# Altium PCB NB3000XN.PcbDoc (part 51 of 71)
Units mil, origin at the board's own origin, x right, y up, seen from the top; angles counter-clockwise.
Board outline 9527.56 x 6929.77 mil, 6 copper layers (Top Layer, GND+SHIELD, MidLayer1, MidLayer2, P2 - 3V3+5V0, Bottom Layer), stack 62.375 mil thick; 832 components, 1027 nets, 4655 pads, 4981 vias.
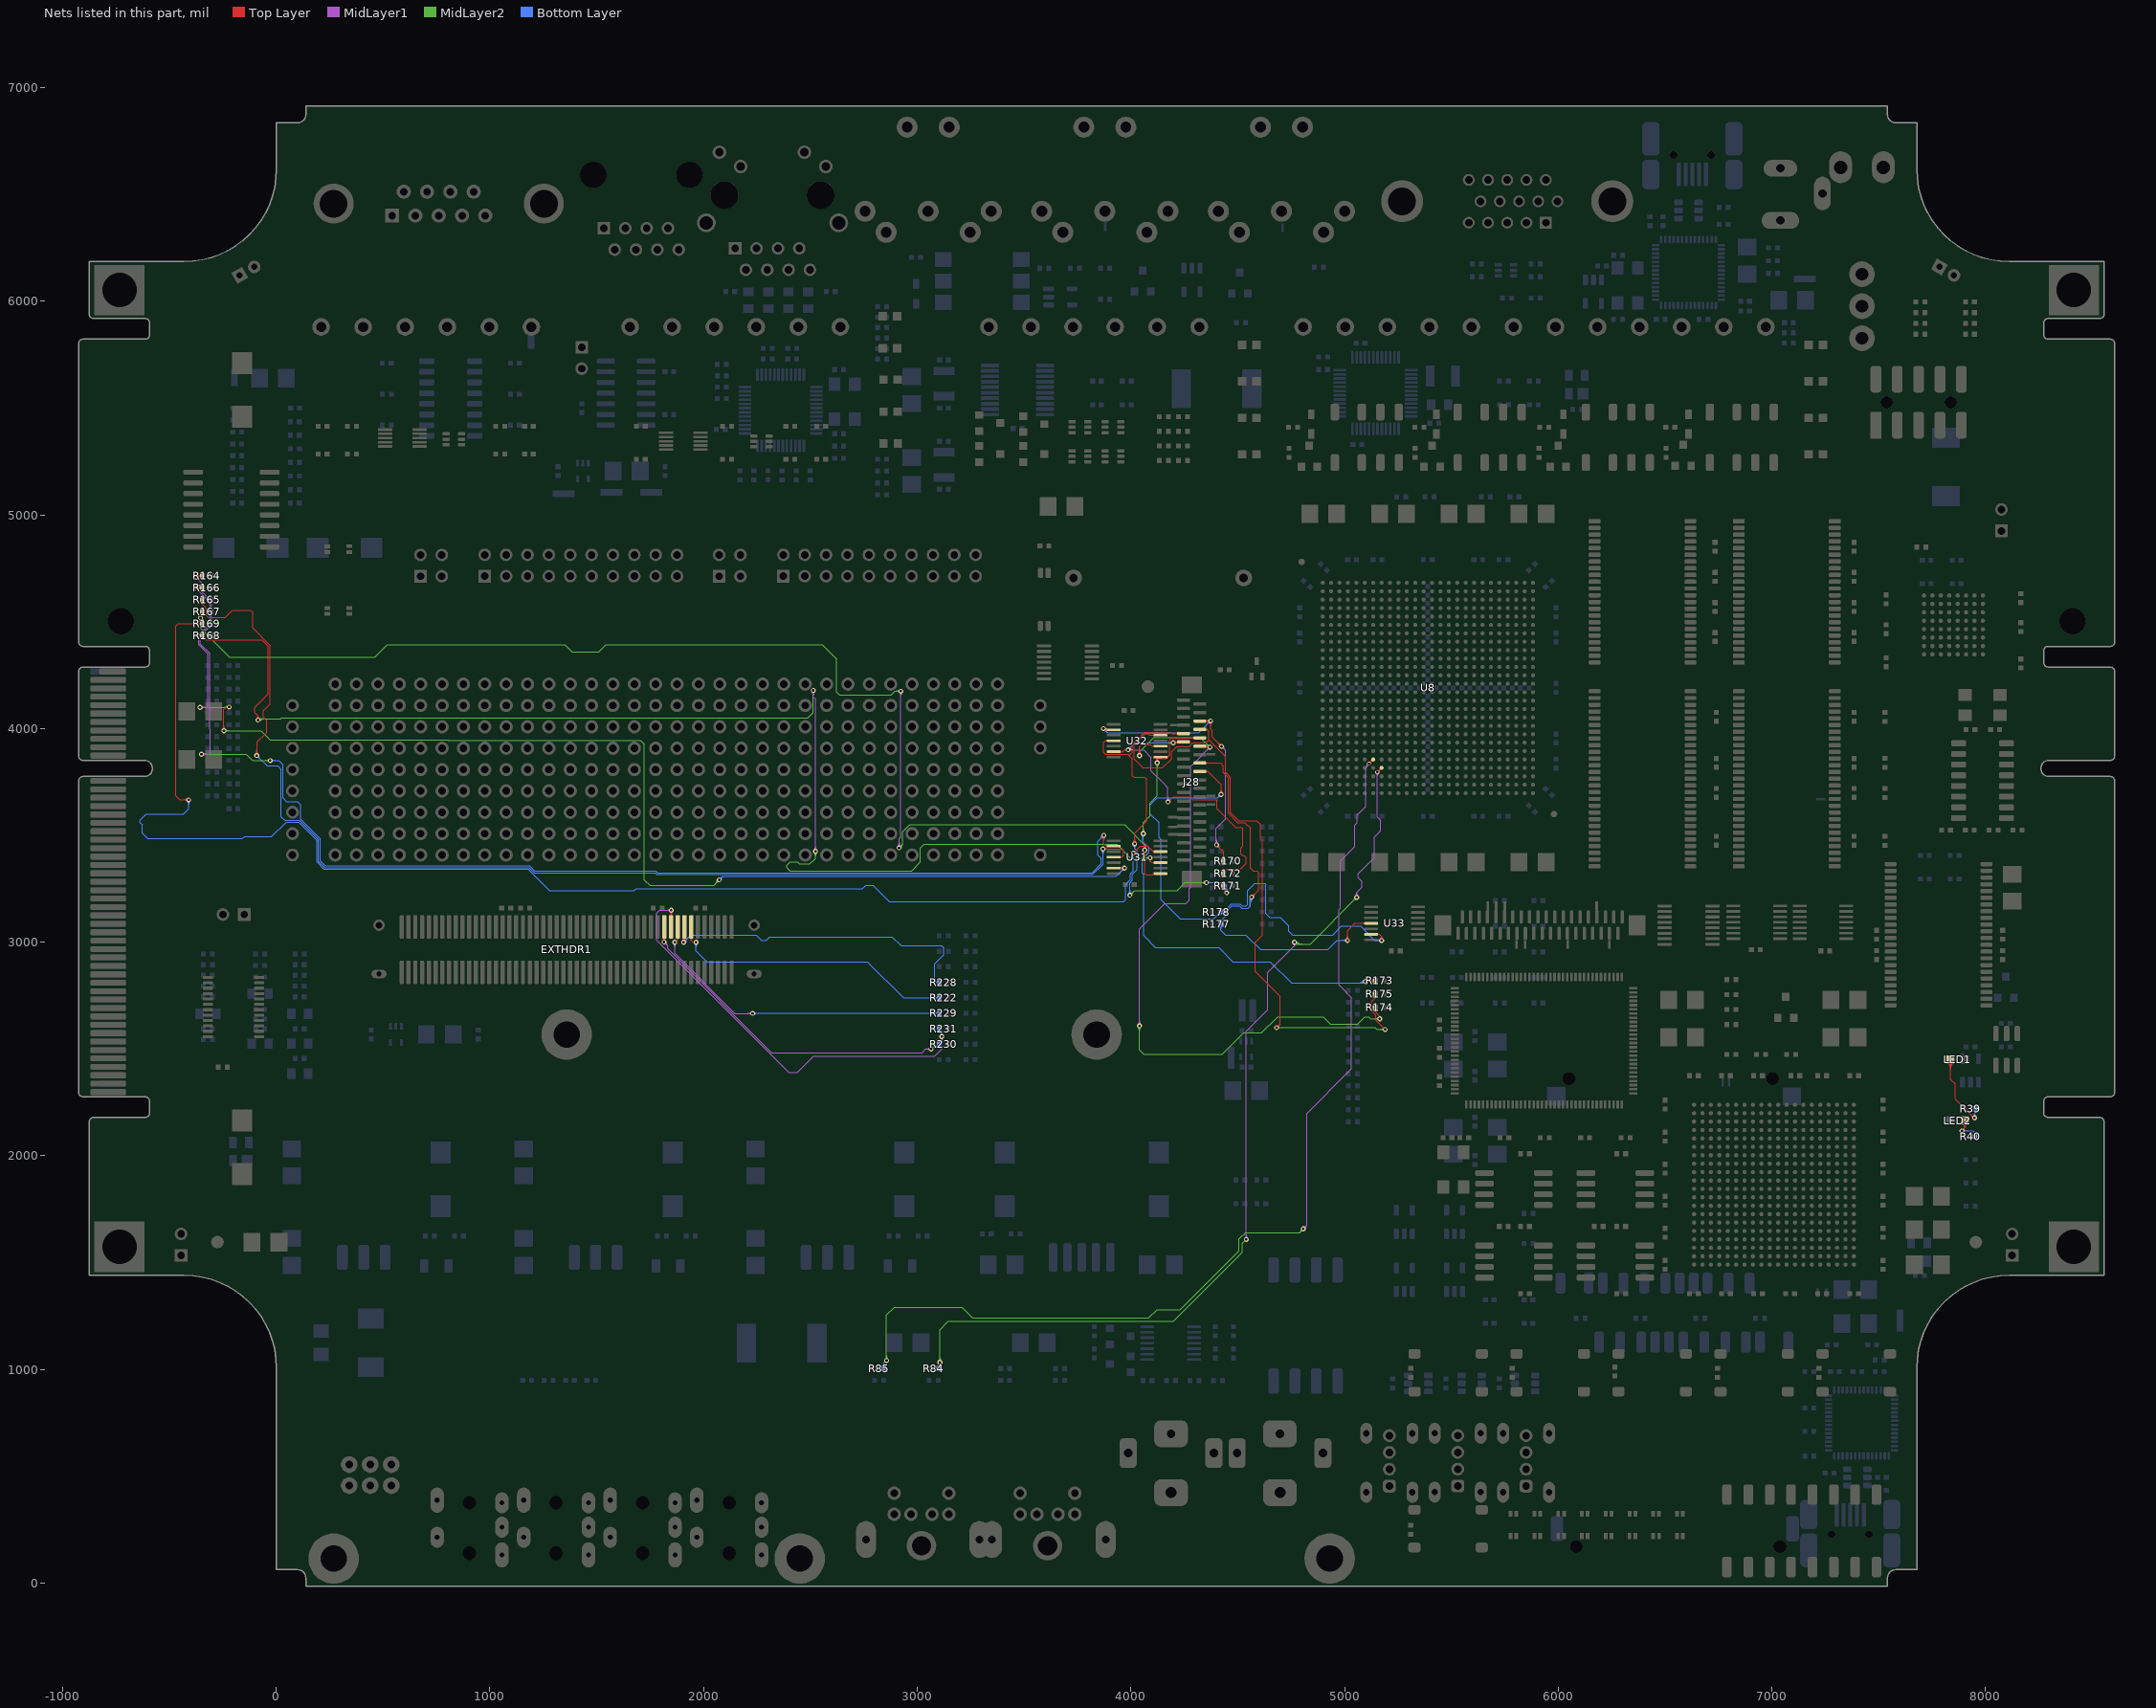
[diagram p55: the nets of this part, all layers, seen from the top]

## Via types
v1: diameter 23, hole 11.81, Top Layer to Bottom Layer, 3672 vias
v2: diameter 26, hole 11.81, Top Layer to Bottom Layer, 461 vias
v3: diameter 19, hole 11.81, Top Layer to Bottom Layer, tented both sides, 396 vias
v4: diameter 23.62, hole 11.81, Top Layer to Bottom Layer, 288 vias
v5: diameter 20, hole 11.81, Top Layer to Bottom Layer, 91 vias
v6: diameter 23, hole 11.81, Top Layer to Bottom Layer, tented both sides, 50 vias
v7: diameter 31, hole 11.81, Top Layer to Bottom Layer, 15 vias
v8: diameter 27.56, hole 11.81, Top Layer to Bottom Layer, tented both sides, 4 vias
v9: diameter 29, hole 11.81, Top Layer to Bottom Layer, 3 vias
v10: diameter 21, hole 11.81, Top Layer to Bottom Layer, 1 vias

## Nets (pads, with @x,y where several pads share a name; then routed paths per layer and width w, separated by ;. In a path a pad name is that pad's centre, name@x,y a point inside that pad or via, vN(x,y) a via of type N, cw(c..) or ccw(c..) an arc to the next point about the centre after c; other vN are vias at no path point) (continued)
JTAG.HARD.TMS: EXTHDR1.13 R222.2 | length 1502
  Top Layer w4: EXTHDR1.13@1936.82,3020.94 cw(c1924.52,3008.04) 1942.35,3008.04 ; EXTHDR1.13@1942.35,3071.85 1942.35,3008.04 ; EXTHDR1.13@1947.87,3020.94 ccw(c1960.18,3008.04) 1942.35,3008.04 ; v1(1965.19,3000.04) 1950.35,3000.04 1942.35,3008.04
  Bottom Layer w4: v1@1958.47,2993.32 cw(c1942.26,2977.11) 1965.19,2977.11 cw(c1988.13,2977.11) v1@1971.91,2993.32 ; v1@1961.3,2996.15 cw(c1951.91,2986.76) 1965.19,2986.76 cw(c1978.47,2986.76) v1@1969.08,2996.15 ; v1(1965.19,3000.04) 1965.19,2958.37 2015.19,2908.37 2767.07,2908.37 2935.44,2740 R222.2@3103.82,2740 ; R222.2@3097.23,2733.41 ccw(c3081.32,2717.5) 3081.32,2740 ccw(c3081.32,2762.5) R222.2@3097.23,2746.59 ; R222.2@3100.06,2736.24 ccw(c3090.98,2727.16) 3090.98,2740 ccw(c3090.98,2752.84) R222.2@3100.06,2743.76
JTAG.SOFT.TCK: EXTHDR1.19 R231.2 | length 2259.8
  Top Layer w4: v1@1841.81,3143.32 cw(c1825.59,3127.11) 1848.52,3127.11 cw(c1871.46,3127.11) v1@1855.24,3143.32 ; EXTHDR1.19@1842.2,3122.62 ccw(c1826.94,3137.89) 1848.52,3137.89 ; v1@1844.64,3146.15 cw(c1835.25,3136.76) 1848.52,3136.76 cw(c1861.8,3136.76) v1@1852.41,3146.15 ; EXTHDR1.19@1845.03,3119.8 ccw(c1836.59,3128.23) 1848.52,3128.23 ; EXTHDR1.19@1847.86,3071.85 1847.86,3091.71 1848.52,3091.71 v1(1848.52,3150.04) ; 1848.52,3134.67 ccw(c1865.56,3134.67) EXTHDR1.19@1853.51,3122.62
  MidLayer1 w4: v1@1840.35,3145.2 ccw(c1831.86,3140.17) 1831.86,3150.04 ccw(c1831.86,3159.91) v1@1840.35,3154.88 ; v1(1848.52,3150.04) 1795.04,3150.04 1781.86,3136.86 1781.86,3008.37 2398.52,2391.71 2440.19,2391.71 2515.19,2466.71 3081.86,2466.71 3115.19,2500.04 v1(3115.19,2558.37) ; v1@3108.47,2551.66 cw(c3092.26,2535.44) 3115.19,2535.44 cw(c3138.13,2535.44) v1@3121.91,2551.66 ; v1@3111.3,2554.49 cw(c3101.91,2545.1) 3115.19,2545.1 cw(c3128.47,2545.1) v1@3119.08,2554.49
  Bottom Layer w4: R231.2@3103.82,2591.71 3103.82,2594.51 R231.2@3103.82,2595 ; R231.2@3103.86,2591.71 3115.19,2580.37 ; R231.2@3104.5,2585.21 cw(c3105.38,2573.33) 3113.81,2581.76 cw(c3119.32,2587.26) R231.2@3112.26,2590.56 ; v1@3108.68,2565.29 ccw(c3094.47,2580.37) 3115.19,2580.37 ; v1@3111.42,2562.38 ccw(c3103.19,2571.11) 3115.19,2571.11 ccw(c3127.19,2571.11) v1@3118.96,2562.38 ; v1(3115.19,2558.37) 3115.19,2580.37 ; v1@3121.7,2565.29 cw(c3135.91,2580.37) 3115.19,2580.37
JTAG.SOFT.TDI: EXTHDR1.15 R228.2 | length 1709.2
  Top Layer w4: v1@1900.14,3006.76 ccw(c1874.28,3032.62) EXTHDR1.15@1910.85,3032.62 ; v1@1902.97,3003.93 ccw(c1883.94,3022.96) EXTHDR1.15@1910.85,3022.96 ; EXTHDR1.15@1905.19,3021.07 cw(c1891.54,3007.42) 1910.85,3007.42 cw(c1930.16,3007.42) EXTHDR1.15@1916.51,3021.07 ; v1@1905.8,3001.1 ccw(c1893.6,3013.3) 1910.85,3013.3 ccw(c1920.15,3013.34) v1@1913.57,3006.76 ; v1(1906.86,3000.04) 1910.85,3004.03 EXTHDR1.15@1910.85,3071.85
  Bottom Layer w4: v1(1906.86,3000.04) 1940.52,3033.71 2246.86,3033.71 2272.19,3008.37 2293.37,3008.37 2310.37,3025.37 2882.39,3025.37 2924.39,2983.37 3113.86,2983.37 3123.52,2973.71 3123.52,2941.71 3081.86,2900.04 3081.86,2820.83 3090.19,2812.5 ; v1@1906.86,3005.54 ccw(c1906.86,3018.82) 1916.25,3009.43 ccw(c1925.64,3000.04) v1@1912.36,3000.04 ; v1@1906.86,3009.54 ccw(c1906.86,3032.48) 1923.07,3016.26 ccw(c1939.29,3000.04) v1@1916.36,3000.04 ; R228.2@3095.13,2809.12 ccw(c3090.19,2807.19) 3090.19,2812.5 ; R228.2@3095.13,2815.88 cw(c3090.19,2817.81) 3090.19,2812.5 ; R228.2@3103.82,2812.5 3090.19,2812.5
JTAG.SOFT.TDO: EXTHDR1.17 R229.2 | length 1716.4
  Top Layer w4: v1(1865.19,3000.04) 1879.35,3014.2 ; EXTHDR1.17@1875.99,3019.47 cw(c1873.55,3014.21) 1879.35,3014.21 ; EXTHDR1.17@1879.35,3071.85 1879.35,3014.2 ; EXTHDR1.17@1882.72,3019.47 ccw(c1885.16,3014.21) 1879.35,3014.21
  MidLayer1 w4: v1@1858.47,2993.32 cw(c1842.26,2977.11) 1865.19,2977.11 cw(c1888.13,2977.11) v1@1871.91,2993.32 ; v1@1861.3,2996.15 cw(c1851.91,2986.76) 1865.19,2986.76 cw(c1878.47,2986.76) v1@1869.08,2996.15 ; v1(1865.19,3000.04) 1865.19,2975 1865.19,2947.67 2146.15,2666.71 v1(2229.86,2666.71) ; v1@2223.14,2659.99 ccw(c2206.92,2643.77) 2206.92,2666.71 ccw(c2206.92,2689.64) v1@2223.14,2673.43 ; v1@2225.97,2662.82 ccw(c2216.58,2653.43) 2216.58,2666.71 ccw(c2216.58,2679.99) v1@2225.97,2670.6
  Bottom Layer w4: v1(2229.86,2666.71) 2230.65,2667.5 R229.2@3103.82,2667.5 ; v1@2233.75,2662.82 cw(c2245.05,2651.52) 2245.05,2667.5 ; v1@2236.57,2659.99 cw(c2254.7,2641.86) 2254.7,2667.5 ; v1@2236.57,2673.43 ccw(c2250.88,2687.73) 2250.88,2667.5 ; R229.2@3097.23,2660.91 ccw(c3081.32,2645) 3081.32,2667.5 ccw(c3081.32,2690) R229.2@3097.23,2674.09 ; R229.2@3100.06,2663.74 ccw(c3090.98,2654.66) 3090.98,2667.5 ccw(c3090.98,2680.34) R229.2@3100.06,2671.26
JTAG.SOFT.TMS: EXTHDR1.21 R230.2 | length 1926.8
  Top Layer w4: v1@1808.47,3007.43 ccw(c1789.43,3026.47) EXTHDR1.21@1816.36,3026.47 ; EXTHDR1.21@1810.7,3021.07 cw(c1797.05,3007.42) 1816.36,3007.42 cw(c1835.67,3007.42) EXTHDR1.21@1822.02,3021.07 ; v1@1811.3,3004.6 ccw(c1799.08,3016.82) EXTHDR1.21@1816.36,3016.82 ; v1(1815.19,3000.71) 1816.36,3001.88 EXTHDR1.21@1816.36,3071.85 ; EXTHDR1.21@1816.36,3020.81 ccw(c1835.3,3020.81) v1@1821.91,3007.43
  MidLayer1 w4: v1(1815.19,3000.71) 1831.33,2984.57 ; v1@1815.22,2991.21 cw(c1815.31,2968.56) 1831.32,2984.57 ; v1@1815.21,2995.21 cw(c1815.26,2982.09) 1824.53,2991.37 cw(c1833.8,3000.64) v1@1820.69,3000.69 ; v1@1824.69,3000.67 ccw(c1847.34,3000.59) 1831.32,2984.57 ; v1@3058.47,2493.32 ccw(c3042.26,2477.11) 3042.26,2500.04 ccw(c3042.26,2522.98) v1@3058.47,2506.76 ; v1@3061.3,2496.15 ccw(c3051.91,2486.76) 3051.91,2500.04 ccw(c3051.91,2513.32) v1@3061.3,2503.93 ; v1(3065.19,2500.04) 3040,2500.04 3023,2483.04 2318.51,2483.04 1831.33,2970.22 1831.33,2984.57
  Bottom Layer w4: v1(3065.19,2500.04) 3075.19,2510.04 ; 3080.57,2510.04 ccw(c3080.57,2529) R230.2@3098.73,2523.54 ; 3085.95,2510.04 ccw(c3085.95,2527.38) R230.2@3102.56,2522.39 ; 3091.33,2510.04 ccw(c3091.33,2525.76) R230.2@3106.39,2521.24 ; R230.2@3094.89,2524.69 cw(c3075.19,2530.62) 3075.19,2510.04 ; 3096.71,2510.04 ccw(c3096.71,2524.15) R230.2@3110.22,2520.08 ; 3102.09,2510.04 ccw(c3102.09,2522.53) R230.2@3114.05,2518.93 ; R230.2@3103.82,2522.5 3103.82,2510.04 3075.19,2510.04
KEYBOARD.CLOCK: R85.1 U8.AB7 | length 5179.3
  Top Layer w4: v3(5114.41,3835.67) U8.AB7@5134.09,3855.35 ; U8.AB7@5126.59,3855.35 cw(c5108.49,3855.35) 5121.29,3842.55 cw(c5134.09,3829.75) U8.AB7@5134.09,3847.85 ; U8.AB7@5126.75,3855.35 cw(c5109.03,3855.35) 5121.56,3842.82 cw(c5134.09,3830.29) U8.AB7@5134.09,3848.01 ; 5127.21,3848.47 cw(c5114.41,3861.28) 5114.41,3843.17 ccw(c5114.41,3861.28) 5127.21,3848.47 ; 5127.21,3848.47 ccw(c5140.02,3835.67) 5121.91,3835.67 cw(c5140.02,3835.67) 5127.21,3848.47
  MidLayer1 w4: v1(4806.86,1658.37) 4823.52,1675.04 4823.52,2198.71 5021.14,2396.33 ; v1@4806.86,1663.87 ccw(c4806.86,1677.15) 4816.25,1667.76 ccw(c4825.64,1658.37) v1@4812.36,1658.37 ; v1@4806.86,1667.87 ccw(c4806.86,1690.81) 4823.08,1674.59 ccw(c4839.29,1658.37) v1@4816.36,1658.37 ; 5020,2395 5033.52,2408.52 5033.52,2740.04 4973.52,2800.04 4973.52,3152.33 4981.19,3160 4981.19,3380.06 5048.52,3447.39 5048.52,3548.69 5060,3560.16 5060,3597.2 5070,3607.2 ; 5070.03,3607.17 5098.9,3636.04 5098.9,3660 5098.9,3670 5098.9,3718.62 5098.9,3812.16 cw(c5112.95,3812.16) 5103.02,3822.09 ; v3@5106.94,3835.02 cw(c5088.9,3833.44) 5102.77,3821.8 cw(c5116.64,3810.16) v3@5115.06,3828.2
  MidLayer2 w4: v1@2850.14,1048.43 ccw(c2833.92,1064.64) 2856.86,1064.64 ccw(c2879.79,1064.64) v1@2863.57,1048.43 ; v1@2852.97,1045.6 ccw(c2843.58,1054.99) 2856.86,1054.99 ccw(c2870.14,1054.99) v1@2860.75,1045.6 ; v1(2856.86,1041.71) 2856.86,1255 2892.73,1290.87 3210,1290.87 3259.83,1241.04 4083.65,1241.04 4122.33,1279.73 4230.79,1279.73 4506.64,1555.58 4506.64,1610.88 4537.13,1641.37 4789.86,1641.37 v1(4806.86,1658.37) ; v1@4797.36,1658.37 cw(c4774.42,1658.37) 4790.64,1642.16 cw(c4806.86,1625.94) v1@4806.86,1648.87 ; v1@4801.36,1658.37 cw(c4788.08,1658.37) 4797.47,1648.99 cw(c4806.86,1639.6) v1@4806.86,1652.87
  Bottom Layer w4: R85.1@2836.64,1012.08 ccw(c2820.73,1027.99) 2843.23,1027.99 ccw(c2865.73,1027.99) R85.1@2849.82,1012.08 ; R85.1@2839.47,1009.25 ccw(c2830.39,1018.33) 2843.23,1018.33 ccw(c2856.07,1018.33) R85.1@2846.99,1009.25 ; R85.1@2843.23,1005 2843.23,1028.08 v1(2856.86,1041.71)
KEYBOARD.DATA: R84.1 U8.AC8 | length 5037
  Top Layer w4: v3(5153.78,3796.3) U8.AC8@5173.46,3815.98 ; U8.AC8@5165.96,3815.98 cw(c5147.86,3815.98) 5160.66,3803.18 cw(c5173.46,3790.38) U8.AC8@5173.46,3808.48 ; U8.AC8@5166.12,3815.98 cw(c5148.4,3815.98) 5160.93,3803.45 cw(c5173.46,3790.92) U8.AC8@5173.46,3808.64 ; 5166.58,3809.1 ccw(c5179.39,3796.3) 5161.28,3796.3 cw(c5179.39,3796.3) 5166.58,3809.1 ; 5166.58,3809.1 cw(c5153.78,3821.91) 5153.78,3803.8 ccw(c5153.78,3821.91) 5166.58,3809.1
  MidLayer1 w4: v1@4533.47,1615.09 ccw(c4517.26,1631.31) 4540.19,1631.31 ccw(c4563.13,1631.31) v1@4546.91,1615.09 ; v1@4536.3,1612.26 ccw(c4526.91,1621.65) 4540.19,1621.65 ccw(c4553.47,1621.65) v1@4544.08,1612.26 ; v1(4540.19,1608.37) 4540.19,2583.37 4640.19,2683.37 4640.19,2858.37 4765.19,2983.37 ; v1@4760.35,2991.87 cw(c4755.32,2983.38) 4765.19,2983.38 ; v1(4765.19,3000.04) 4765.19,2983.37 ; v1@4770.03,2991.87 ccw(c4775.06,2983.38) 4765.19,2983.38 ; v1@5050.31,3216.59 ccw(c5035.79,3231.86) 5056.86,3231.86 ; v1@5053.07,3213.69 ccw(c5044.66,3222.53) 5056.86,3222.53 ccw(c5069.05,3222.53) v1@5060.65,3213.69 ; v1(5056.86,3209.71) 5056.86,3231.86 ; v1@5063.4,3216.59 cw(c5077.92,3231.86) 5056.86,3231.86 ; v3@5148.48,3791 cw(c5135.67,3778.19) 5153.78,3778.19 cw(c5171.89,3778.19) v3@5159.08,3791 ; v3@5148.59,3791.11 cw(c5136.05,3778.57) 5153.78,3778.57 cw(c5171.51,3778.57) v3@5158.97,3791.11 ; v3(5153.78,3796.3) 5153.78,3718.62 5153.78,3670 5153.78,3660 5153.78,3586.45 5168.52,3571.71 5168.52,3520.65 5140.86,3492.98 5140.86,3395.36 5080.5,3335 5079.19,3335 5064.19,3320 5064.19,3301.04 5081.86,3283.37 5081.86,3256.86 5056.86,3231.86
  MidLayer2 w4: v1@3100.14,1040.09 ccw(c3083.92,1056.31) 3106.86,1056.31 ccw(c3129.79,1056.31) v1@3113.57,1040.09 ; v1@3102.97,1037.26 ccw(c3093.58,1046.65) 3106.86,1046.65 ccw(c3120.14,1046.65) v1@3110.75,1037.26 ; v1(3106.86,1033.37) 3106.86,1186.86 3145.04,1225.04 4198.73,1225.04 4522.64,1548.95 4522.64,1590.82 v1(4540.19,1608.37) ; v1@4763.42,2998.27 ccw(c4779.27,3014.12) 4779.27,2991.71 ; v1(4765.19,3000.04) 4765.19,2993.37 4766.86,2991.71 4838.86,2991.71 v1(5056.86,3209.71) ; v1@4766.25,3001.1 ccw(c4788.93,3023.78) 4788.93,2991.71 ; v1@4769.08,3003.93 ccw(c4798.59,3033.44) 4798.59,2991.71 ; v1@4771.91,3006.76 ccw(c4808.24,3043.09) 4808.24,2991.71 ; v1@5047.36,3209.71 cw(c5024.42,3209.71) 5040.64,3193.49 cw(c5056.86,3177.27) v1@5056.86,3200.21 ; v1@5051.36,3209.71 cw(c5038.08,3209.71) 5047.47,3200.32 cw(c5056.86,3190.93) v1@5056.86,3204.21
  Bottom Layer w4: R84.1@3094.88,1013.79 ccw(c3084.85,1033.37) v1(3106.86,1033.37) 3106.86,1000.04 3099.13,1000.04 R84.1@3099.13,1005 ; R84.1@3096.71,1010.23 ccw(c3088.2,1026.83) v1@3106.86,1026.83 ; R84.1@3098.53,1006.67 ccw(c3091.55,1020.29) 3106.86,1020.29 ; v1@3100.14,1026.66 cw(c3083.92,1010.44) 3106.86,1010.44 cw(c3129.79,1010.44) v1@3113.57,1026.66 ; v1@3102.97,1029.49 cw(c3093.58,1020.1) 3106.86,1020.1 cw(c3120.14,1020.1) v1@3110.75,1029.49
LED1_BLUE_EXTA: R165.2 U31.4 | length 5977.9
  Top Layer w4: R165.2@-351.93,4595.17 cw(c-361.16,4583.38) -346.18,4583.38 ; R165.2@-346.18,4603 -346.18,4583.37 ; R165.2@-340.44,4595.17 ccw(c-331.2,4583.38) -346.18,4583.38 ; v1@-97.86,3880.43 ccw(c-114.08,3896.64) -91.14,3896.64 ccw(c-68.21,3896.64) v1@-84.43,3880.43 ; v1@-95.03,3877.6 ccw(c-104.42,3886.99) -91.14,3886.99 ccw(c-77.86,3886.99) v1@-87.25,3877.6 ; v1(-91.14,3873.71) -91.14,3902.54 -89,3904.69 -89,3937.16 -45,3981.16 -45,4036.25 -59.81,4051.06 -59.81,4084.13 ; -59.81,4084.81 -59.81,4084.13 ; v1(3869.19,3436.37) 3956.52,3436.37 3967.19,3425.71 3967.19,3408.23 3957.19,3398.23 U31.4@3920,3398.23 ; v1@3873.08,3432.49 cw(c3882.47,3423.1) 3882.47,3436.37 cw(c3882.47,3449.65) v1@3873.08,3440.26 ; v1@3875.91,3429.66 cw(c3892.13,3413.44) 3892.13,3436.37 cw(c3892.13,3459.31) v1@3875.91,3443.09 ; U31.4@3949.31,3395.4 cw(c3956.14,3388.57) 3956.14,3398.23 cw(c3956.14,3407.89) U31.4@3949.31,3401.06 ; -346.18,4583.37 -326.48,4563.67 -326.48,4530 -316.48,4520 -240,4520 -205,4555 -120,4555 -110,4545 -110,4470 -29,4389 -29,4114.94 -59.81,4084.13
  Bottom Layer w4: v1@-91.14,3864.21 cw(c-91.14,3841.27) -74.93,3857.49 cw(c-58.71,3873.71) v1@-81.64,3873.71 ; v1@-91.14,3868.21 cw(c-91.14,3854.93) -81.75,3864.32 cw(c-72.36,3873.71) v1@-85.64,3873.71 ; v1(-91.14,3873.71) -42.48,3825.04 6.86,3825.04 23.52,3808.37 23.52,3586.48 40,3570 108.88,3570 198.52,3480.35 198.52,3400 198.52,3377.98 226.46,3350.04 1181.86,3350.04 1206.86,3325.04 1773.52,3325.04 1781.86,3316.71 3821.71,3316.71 3869.19,3364.19 v1(3869.19,3436.37) ; v1@3862.47,3429.66 cw(c3846.26,3413.44) 3869.19,3413.44 cw(c3892.13,3413.44) v1@3875.91,3429.66 ; v1@3865.3,3432.49 cw(c3855.91,3423.1) 3869.19,3423.1 cw(c3882.47,3423.1) v1@3873.08,3432.49
LED1_GREEN_EXTA: R166.2 U31.6 | length 6570.3
  Top Layer w4: v1(-365,4665) -365,4661.52 v1@-367.52,4659 ; v1@-359.6,4666.05 ccw(c-351.04,4667.73) R166.2@-351.04,4659 ; R166.2@-355.68,4666.82 ccw(c-346.18,4668.67) R166.2@-346.18,4659 v1@-367.52,4659 ; R166.2@-353.02,4652.67 ccw(c-367.52,4639.24) v1@-367.52,4659 ; R166.2@-353.02,4665.33 cw(c-367.52,4678.76) v1@-367.52,4659 ; R166.2@-350.08,4655.39 ccw(c-358.36,4647.72) -358.36,4659 ccw(c-358.36,4670.28) R166.2@-350.08,4662.61 ; v1@-251.72,3996.43 ccw(c-267.94,4012.64) -245,4012.64 ccw(c-222.07,4012.64) v1@-238.28,3996.43 ; v1@-248.89,3993.6 ccw(c-258.28,4002.99) -245,4002.99 ccw(c-231.72,4002.99) v1@-241.11,3993.6 ; v1(-245,3989.71) -245,4090 -235,4100 v1@-225,4100 ; U31.6@3920,3347.05 v1(3970.19,3347.04) ; U31.6@3947.24,3347.05 cw(c3947.24,3324.09) v1@3963.47,3340.32 ; U31.6@3947.27,3347.05 ccw(c3947.27,3369.96) v1@3963.47,3353.76 ; U31.6@3949.31,3344.22 cw(c3956.14,3337.39) 3956.14,3347.05 cw(c3956.14,3356.71) U31.6@3949.31,3349.88 ; 3956.9,3347.05 cw(c3956.9,3333.75) v1@3966.3,3343.15 ; 3956.93,3347.05 ccw(c3956.93,3360.3) v1@3966.3,3350.93 ; v1@-367.52,4659 -376.48,4650.04 v1@-367.52,4659
  MidLayer1 w4: v1@-370.76,4657.44 cw(c-379.62,4645.82) -365,4645.82 ; v1(-365,4665) -365,4645.81 ; v1@-359.24,4657.44 ccw(c-350.38,4645.82) -365,4645.82 ; v1(-356.73,4099.58) -324.42,4099.58 -319,4105 -319,4349 -362.5,4392.5 -362.5,4437.75 -309.62,4490.63 -309.62,4589.37 -310.16,4589.91 ; v1@-352.84,4095.69 cw(c-343.45,4086.31) -343.45,4099.58 cw(c-343.45,4112.86) v1@-352.84,4103.47 ; v1@-350.01,4092.87 cw(c-333.79,4076.65) -333.79,4099.58 cw(c-333.79,4122.52) v1@-350.01,4106.3 ; -309.62,4590.44 -365,4645.81
  MidLayer2 w4: v1(-356.73,4099.58) -356.31,4100 v1@-220,4100 ; v1@-352.84,4095.69 cw(c-342.44,4085.3) -342.44,4100 ; v1@-352.84,4103.47 ccw(c-344.45,4111.86) -344.45,4100 ; v1@-350.01,4092.87 cw(c-332.79,4075.64) -332.79,4100 ; v1@-350.01,4106.3 ccw(c-334.8,4121.51) -334.8,4100 ; -245.35,4100 ccw(c-245.35,4126.35) v1@-226.72,4107.72 ; v1(-245,3989.71) -71.02,3989.71 -29.19,3947.87 802.36,3947.87 805,3945.23 1704.77,3945.23 1723.52,3926.48 1723.52,3291.71 1748.52,3266.71 2048.52,3266.71 v1(2073.52,3291.71) ; v1@-241.11,3985.82 cw(c-231.72,3976.43) -231.72,3989.71 cw(c-231.72,4002.99) v1@-241.11,3993.6 ; -240.52,4100 cw(c-240.52,4080.48) v1@-226.72,4094.28 ; v1@-238.28,3982.99 cw(c-222.07,3966.77) -222.07,3989.71 cw(c-222.07,4012.64) v1@-238.28,3996.43 ; -235.69,4100 ccw(c-235.69,4116.69) v1@-223.89,4104.89 ; v1@2064.02,3291.71 cw(c2041.09,3291.71) 2057.31,3275.49 cw(c2073.52,3259.27) v1@2073.52,3282.21 ; v1@2068.02,3291.71 cw(c2054.75,3291.71) 2064.14,3282.32 cw(c2073.52,3272.93) v1@2073.52,3286.21
  Bottom Layer w4: v1(2073.52,3291.71) 2090.19,3308.37 3931.52,3308.37 v1(3970.19,3347.04) ; v1@2073.52,3297.21 ccw(c2073.52,3310.49) 2082.91,3301.1 ccw(c2092.3,3291.71) v1@2079.02,3291.71 ; v1@2073.52,3301.21 ccw(c2073.52,3324.14) 2089.74,3307.93 ccw(c2105.96,3291.71) v1@2083.02,3291.71 ; v1@3960.69,3347.04 cw(c3937.76,3347.04) 3953.97,3330.82 cw(c3970.19,3314.61) v1@3970.19,3337.54 ; v1@3964.69,3347.04 cw(c3951.41,3347.04) 3960.8,3337.65 cw(c3970.19,3328.26) v1@3970.19,3341.54
  other v1: -220,4101
LED1_RED_EXTA: R164.2 U31.2 | length 6388.5
  Top Layer w4: v1(-376.48,4708.37) -369.85,4715 R164.2@-346.18,4715 ccw(c-346.18,4687.98) v1@-368.6,4703.07 ; v1@-375.23,4707.54 cw(c-361.21,4698.1) -361.21,4715 ; v1@-371.91,4705.3 cw(c-353.7,4693.04) R164.2@-353.7,4715 ; R164.2@-352.77,4708.41 ccw(c-368.68,4692.5) -368.68,4715 ccw(c-368.68,4737.5) R164.2@-352.77,4721.59 ; R164.2@-349.94,4711.24 ccw(c-359.02,4702.16) -359.02,4715 ccw(c-359.02,4727.84) R164.2@-349.94,4718.76 ; v1@3866.81,3493.32 cw(c3850.59,3477.11) 3873.52,3477.11 cw(c3896.46,3477.11) v1@3880.24,3493.32 ; v1@3869.64,3496.15 cw(c3860.25,3486.76) 3873.52,3486.76 cw(c3886.8,3486.76) v1@3877.41,3496.15 ; v1(3873.52,3500.04) 3873.52,3461.4 3885.52,3449.41 ; U31.2@3890.32,3447.01 ccw(c3885.52,3443.41) 3885.52,3449.41 ; U31.2@3890.32,3451.81 cw(c3885.52,3455.41) 3885.52,3449.41 ; U31.2@3920,3449.41 3885.52,3449.41
  MidLayer1 w4: v1@-376.48,4698.87 cw(c-376.48,4675.94) -360.26,4692.16 cw(c-344.04,4708.37) v1@-366.98,4708.37 ; v1@-376.48,4702.87 cw(c-376.48,4689.6) -367.09,4698.99 cw(c-357.7,4708.37) v1@-370.98,4708.37 ; v1(-376.48,4708.37) -345,4676.9 -345,4637.13 -301.62,4593.75 -301.62,4487.31 -354.5,4434.44 -354.5,4395.81 -311,4352.31 -311,3998.61 -309.23,3996.83 -309.23,3887 -316.23,3880 v1(-350,3880) ; v1@-346.11,3876.11 cw(c-336.72,3866.72) -336.72,3880 cw(c-336.72,3893.28) v1@-346.11,3883.89 ; v1@-343.28,3873.28 cw(c-327.07,3857.06) -327.07,3880 cw(c-327.07,3902.93) v1@-343.28,3886.72
  MidLayer2 w4: v1(-350,3880) -140,3880 -118.24,3858.24 -110.04,3850.04 v1(-28.14,3850.04) ; v1@-346.11,3876.11 cw(c-336.72,3866.72) -336.72,3880 cw(c-336.72,3893.28) v1@-346.11,3883.89 ; v1@-343.28,3873.28 cw(c-327.07,3857.06) -327.07,3880 cw(c-327.07,3902.93) v1@-343.28,3886.72 ; v1@-34.86,3843.32 ccw(c-51.08,3827.11) -51.08,3850.04 ccw(c-51.08,3872.98) v1@-34.86,3856.76 ; v1@-32.03,3846.15 ccw(c-41.42,3836.76) -41.42,3850.04 ccw(c-41.42,3863.32) v1@-32.03,3853.93
  Bottom Layer w4: v1(-28.14,3850.04) 11.52,3850.04 31.86,3829.71 31.86,3675.04 48.52,3658.37 98.52,3658.37 115.19,3641.71 115.19,3575 206.86,3483.33 206.86,3380.96 229.78,3358.04 1185.17,3358.04 1210.17,3333.04 1776.84,3333.04 1784.84,3325.04 3818.73,3325.04 3861.19,3367.5 3861.19,3391.19 3845,3407.38 3845,3471.52 v1(3873.52,3500.04) ; v1@-24.25,3846.15 cw(c-14.86,3836.76) -14.86,3850.04 cw(c-14.86,3863.32) v1@-24.25,3853.93 ; v1@-21.43,3843.32 cw(c-5.21,3827.11) -5.21,3850.04 cw(c-5.21,3872.98) v1@-21.43,3856.76 ; v1@3864.02,3500.04 cw(c3841.09,3500.04) 3857.31,3483.82 cw(c3873.52,3467.61) v1@3873.52,3490.54 ; v1@3868.02,3500.04 cw(c3854.75,3500.04) 3864.14,3490.65 cw(c3873.52,3481.26) v1@3873.52,3494.54
LED2_BLUE_EXTA: R168.2 U31.10 | length 6747.9
  Top Layer w4: R168.2@-346.18,4425.19 cw(c-346.18,4401.5) -329.43,4418.25 ; R168.2@-346.18,4429.19 cw(c-346.18,4415.16) R168.2@-336.26,4425.08 ; R168.2@-346.18,4435 -326.18,4415 -66.31,4415 -37,4385.69 -37,4163 -100,4100 -100,4075 -85,4060 v1(-85,4040) v1@-80,4045 ; R168.2@-340.86,4434.51 ccw(c-329.21,4434.51) R168.2@-337.45,4426.27 ; R168.2@-336.86,4434.51 ccw(c-315.55,4434.51) -330.62,4419.44 ; v1@-91,4047.36 ccw(c-101.3,4060) -85,4060 ccw(c-68.7,4060) v1@-79,4047.36 ; v1@-88.47,4044.26 ccw(c-94.44,4051.58) -85,4051.58 ccw(c-75.56,4051.58) v1@-81.53,4044.26 ; v1(4090.19,3394.71) 4090.19,3379.81 4097.36,3372.64 U31.10@4138.5,3372.64 ; U31.10@4109.2,3369.81 ccw(c4102.37,3362.98) 4102.37,3372.64 ccw(c4102.37,3382.29) U31.10@4109.2,3375.47
  MidLayer1 w4: v1@2507.14,4171.99 cw(c2490.92,4155.77) 2513.86,4155.77 cw(c2536.79,4155.77) v1@2520.57,4171.99 ; v1@2509.97,4174.82 cw(c2500.58,4165.43) 2513.86,4165.43 cw(c2527.14,4165.43) v1@2517.75,4174.82 ; v1(2513.86,4178.71) 2513.86,4149.67 2523.52,4140 v1(2523.52,3425.04) ; v1@2516.81,3431.76 ccw(c2500.59,3447.98) 2523.52,3447.98 ccw(c2546.46,3447.98) v1@2530.24,3431.76 ; v1@2519.64,3428.93 ccw(c2510.25,3438.32) 2523.52,3438.32 ccw(c2536.8,3438.32) v1@2527.41,3428.93
  MidLayer2 w4: v1@-83.94,4038.94 cw(c-69.31,4024.31) -69.31,4045 ; v1@-81.52,4045 19.96,4045 25,4050.04 2488.86,4050.04 2513.86,4075.04 v1(2513.86,4178.71) ; v1@-81.11,4036.11 cw(c-59.65,4014.65) -59.65,4045 ; v1@-78.28,4033.28 cw(c-49.99,4004.99) -49.99,4045 ; v1@-78.28,4046.72 ccw(c-74.14,4050.86) -74.14,4045 ; v1@2507.14,4171.99 cw(c2490.92,4155.77) 2513.86,4155.77 cw(c2536.79,4155.77) v1@2520.57,4171.99 ; v1@2509.97,4174.82 cw(c2500.58,4165.43) 2513.86,4165.43 cw(c2527.14,4165.43) v1@2517.75,4174.82 ; v1@2516.81,3418.32 cw(c2500.59,3402.11) 2523.52,3402.11 cw(c2546.46,3402.11) v1@2530.24,3418.32 ; v1@2519.64,3421.15 cw(c2510.25,3411.76) 2523.52,3411.76 cw(c2536.8,3411.76) v1@2527.41,3421.15 ; v1(2523.52,3425.04) 2523.52,3391.71 2498.52,3366.71 2448.52,3366.71 2440.19,3375.04 2405.86,3375.04 2390.19,3359.37 2390.19,3349.04 2405.86,3333.37 2973.52,3333.37 3015.19,3375.04 3015.19,3441.71 3031.86,3458.37 3934.86,3458.37 3998.52,3394.71 v1(4090.19,3394.71) ; v1@4083.47,3387.99 ccw(c4067.26,3371.77) 4067.26,3394.71 ccw(c4067.26,3417.64) v1@4083.47,3401.43 ; v1@4086.3,3390.82 ccw(c4076.91,3381.43) 4076.91,3394.71 ccw(c4076.91,3407.99) v1@4086.3,3398.6
LED2_GREEN_EXTA: R169.2 U31.12 | length 6883
  Top Layer w4: v1@-416.53,3659.99 ccw(c-432.74,3643.77) -432.74,3666.71 ccw(c-432.74,3689.64) v1@-416.53,3673.43 ; v1@-413.7,3662.82 ccw(c-423.09,3653.43) -423.09,3666.71 ccw(c-423.09,3679.99) v1@-413.7,3670.6 ; v1(-409.81,3666.71) -451.71,3666.71 -469,3684 -469,4481 -459,4491 R169.2@-346.18,4491 ; R169.2@-352.77,4484.41 ccw(c-368.68,4468.5) -368.68,4491 ccw(c-368.68,4513.5) R169.2@-352.77,4497.59 ; R169.2@-349.94,4487.24 ccw(c-359.02,4478.16) -359.02,4491 ccw(c-359.02,4503.84) R169.2@-349.94,4494.76 ; v1(4011.86,3416.71) 4045.19,3450.04 4078.97,3450.04 4105.19,3423.82 ; v1@4011.86,3422.21 ccw(c4011.86,3435.49) 4021.25,3426.1 ccw(c4030.64,3416.71) v1@4017.36,3416.71 ; v1@4011.86,3426.21 ccw(c4011.86,3449.14) 4028.07,3432.93 ccw(c4044.29,3416.71) v1@4021.36,3416.71 ; 4093.53,3435.48 ccw(c4112.02,3453.97) U31.12@4112.02,3427.82 ; 4100.36,3428.65 ccw(c4112.02,3440.32) U31.12@4112.02,3423.82 ; U31.12@4108.54,3421.86 ccw(c4105.19,3419.98) 4105.19,3423.82 ; U31.12@4108.54,3425.78 cw(c4105.19,3427.66) 4105.19,3423.82 ; U31.12@4138.5,3423.82 4105.19,3423.82
  Bottom Layer w4: v1@-416.53,3659.99 cw(c-432.74,3643.77) -409.81,3643.77 cw(c-386.87,3643.77) v1@-403.09,3659.99 ; v1@-413.7,3662.82 cw(c-423.09,3653.43) -409.81,3653.43 cw(c-396.53,3653.43) v1@-405.92,3662.82 ; v1(-409.81,3666.71) -409.81,3625.19 -434.5,3600.5 -609.1,3600.5 -638.26,3571.34 -638.26,3560.5 -627.5,3549.73 -627.5,3509.65 -602.85,3485 -157.43,3485 -148.22,3494.21 -20.79,3494.21 47,3562 105.56,3562 190.19,3477.37 190.19,3375 223.15,3342.04 1178.54,3342.04 1279.58,3241 1674.94,3241 1683.65,3249.71 2743,3249.71 2760,3266.71 2793.29,3266.71 2868.96,3191.04 3966.04,3191.04 3975,3200 3975,3269.46 3998.52,3292.98 3998.52,3320.96 4011.86,3334.29 v1(4011.86,3416.71)
LED2_RED_EXTA: R167.2 U31.8 | length 6413.1
  Top Layer w4: v1@-360.33,4525.5 ccw(c-372.02,4539.06) R167.2@-354.12,4539.06 ; v1@-357.72,4522.48 ccw(c-364.49,4530.32) -354.12,4530.32 ccw(c-343.76,4530.32) v1@-350.53,4522.48 ; v1@-354.12,4517.21 cw(c-329.96,4517.21) R167.2@-341.67,4538.36 ; v1(-354.12,4518.31) R167.2@-354.12,4539.06 ; v1@-354.12,4524 cw(c-333.72,4524) R167.2@-343.6,4541.85 ; -354.12,4530.79 cw(c-337.48,4530.79) R167.2@-345.54,4545.35 ; R167.2@-354.12,4537.58 cw(c-341.24,4537.58) R167.2@-347.48,4548.85 ; v1@-347.92,4525.5 cw(c-336.23,4539.06) R167.2@-354.12,4539.06 ; R167.2@-346.18,4547 R167.2@-354.12,4539.06 ; v1@4058.47,3423.99 cw(c4042.26,3407.77) 4065.19,3407.77 cw(c4088.13,3407.77) v1@4071.91,3423.99 ; v1@4061.3,3426.82 cw(c4051.91,3417.43) 4065.19,3417.43 cw(c4078.47,3417.43) v1@4069.08,3426.82 ; v1(4065.19,3430.71) 4065.19,3321.04 4071.77,3314.46 4100,3314.46 4107,3321.46 U31.8@4138.5,3321.46 ; 4103.86,3318.31 cw(c4111.48,3310.69) U31.8@4112.02,3321.46
  MidLayer1 w4: v1@2908.47,3448.43 ccw(c2892.26,3464.64) 2915.19,3464.64 ccw(c2938.13,3464.64) v1@2921.91,3448.43 ; v1@2911.3,3445.6 ccw(c2901.91,3454.99) 2915.19,3454.99 ccw(c2928.47,3454.99) v1@2919.08,3445.6 ; v1(2915.19,3441.71) 2915.19,3485.19 2923.52,3493.52 v1(2923.52,4175) ; v1@2916.81,4168.28 cw(c2900.59,4152.06) 2923.52,4152.06 cw(c2946.46,4152.06) v1@2930.24,4168.28 ; v1@2919.64,4171.11 cw(c2910.25,4161.72) 2923.52,4161.72 cw(c2936.8,4161.72) v1@2927.41,4171.11
  MidLayer2 w4: v1@-360.84,4511.59 cw(c-377.06,4495.38) -354.12,4495.38 cw(c-331.19,4495.38) v1@-347.41,4511.59 ; v1@-358.01,4514.42 cw(c-367.4,4505.03) -354.12,4505.03 cw(c-340.85,4505.03) v1@-350.24,4514.42 ; v1(-354.12,4518.31) -354.12,4468.69 -218.81,4333.37 462.52,4333.37 520.86,4391.71 1351.51,4391.71 1384.84,4358.37 1510,4358.37 1543.67,4392.04 2556.52,4392.04 2623.52,4325.04 2623.52,4172.06 2637.21,4158.37 2878.86,4158.37 2895.48,4175 v1(2923.52,4175) ; v1(2915.19,3441.71) 2931.86,3458.37 2931.86,3516.71 2965.19,3550.04 3969.96,3550.04 4065.19,3454.81 v1(4065.19,3430.71) ; v1@2915.19,3447.21 ccw(c2915.19,3460.49) 2924.58,3451.1 ccw(c2933.97,3441.71) v1@2920.69,3441.71 ; v1@2915.19,3451.21 ccw(c2915.19,3474.14) 2931.41,3457.93 ccw(c2947.63,3441.71) v1@2924.69,3441.71 ; v1@2916.81,4168.28 ccw(c2900.59,4152.06) 2900.59,4175 ccw(c2900.59,4197.93) v1@2916.81,4181.72 ; v1@2919.64,4171.11 ccw(c2910.25,4161.72) 2910.25,4175 ccw(c2910.25,4188.28) v1@2919.64,4178.89 ; v1@4058.47,3437.43 ccw(c4042.26,3453.64) 4065.19,3453.64 ccw(c4088.13,3453.64) v1@4071.91,3437.43 ; v1@4061.3,3434.6 ccw(c4051.91,3443.99) 4065.19,3443.99 ccw(c4078.47,3443.99) v1@4069.08,3434.6
LED_PGM: LED2.2 R40.2 | length 297.9
  Top Layer w4: v1(7890.19,2116.71) 7903.47,2129.98 ; LED2.2@7892.97,2150.77 cw(c7877.64,2129.98) 7903.47,2129.98 ; LED2.2@7895.34,2153.99 cw(c7883.48,2137.9) 7903.47,2137.9 cw(c7923.45,2137.9) LED2.2@7911.59,2153.99 ; LED2.2@7903.47,2165 7903.47,2129.98 ; LED2.2@7913.96,2150.77 ccw(c7929.29,2129.98) 7903.47,2129.98
  Bottom Layer w4: v1(7890.19,2116.71) 7941.18,2116.71 7951.18,2106.71 ; v1@7894.08,2112.82 cw(c7903.47,2103.43) 7903.47,2116.71 cw(c7903.47,2129.99) v1@7894.08,2120.6 ; v1@7896.91,2109.99 cw(c7913.13,2093.77) 7913.13,2116.71 cw(c7913.13,2139.64) v1@7896.91,2123.43 ; R40.2@7946.49,2098.54 ccw(c7941.73,2106.71) 7951.18,2106.71 ; R40.2@7951.18,2090 7951.18,2106.71 ; R40.2@7955.87,2098.54 cw(c7960.63,2106.71) 7951.18,2106.71
LED_PWR: LED1.1 R39.2 | length 645.1
  Top Layer w4: LED1.1@7824.03,2437.49 cw(c7793.84,2407.31) 7836.54,2407.31 cw(c7879.23,2407.3) LED1.1@7849.04,2437.49 ; LED1.1@7826.86,2440.32 cw(c7803.5,2416.96) 7836.54,2416.96 cw(c7869.57,2416.96) LED1.1@7846.21,2440.32 ; LED1.1@7829.69,2443.15 cw(c7813.15,2426.62) 7836.54,2426.62 cw(c7859.92,2426.62) LED1.1@7843.38,2443.15 ; LED1.1@7836.54,2450 7836.54,2357.37 7857.54,2336.37 7857.54,2266.03 7945.86,2177.71 v1(7948.52,2177.71) ; 7927.75,2195.81 ccw(c7948.52,2216.58) v1@7948.52,2187.21 ; 7934.19,2189.37 cw(c7922.53,2177.71) v1@7939.02,2177.71 ; 7934.58,2188.98 ccw(c7948.52,2202.92) v1@7948.52,2183.21
  Bottom Layer w4: v1@7943.16,2185.55 ccw(c7936.22,2195.71) 7948.52,2195.71 ; R39.2@7944.89,2212.63 cw(c7931.86,2198.37) 7951.18,2198.37 ; R39.2@7947.59,2215.58 cw(c7940.15,2207.44) 7951.18,2207.44 cw(c7962.21,2207.44) R39.2@7954.77,2215.58 ; v1(7948.52,2177.71) 7948.52,2195.71 ; R39.2@7951.18,2220 7951.18,2198.36 ; v1@7953.88,2185.55 cw(c7960.83,2195.71) 7948.52,2195.71 ; R39.2@7957.47,2212.63 ccw(c7970.51,2198.37) 7951.18,2198.37 ; 7948.52,2195.71 7951.18,2198.36
LEDS#.LED0.BLUE: J28.9 R171.2 U32.4 | length 2336.2
  Top Layer w4: U32.4@3890.69,3940.4 ccw(c3883.86,3933.57) 3883.86,3943.23 ccw(c3883.86,3952.89) U32.4@3890.69,3946.06 ; U32.4@3920,3943.23 3881.86,3943.23 3873.52,3934.89 3873.52,3887.71 3881.86,3879.37 3985.86,3879.37 ; v4@4010.41,3467.28 ccw(c3993.67,3484.03) 4017.35,3484.03 ccw(c4041.04,3484.03) v4@4024.29,3467.28 ; v4@4013.24,3464.46 ccw(c4003.32,3474.38) 4017.35,3474.38 ccw(c4031.38,3474.38) v4@4021.46,3464.46 ; v4(4017.35,3460.35) 4017.35,3510.73 4073.52,3566.9 4073.52,3763.18 4065,3771.71 4015.19,3771.71 4006.86,3780.04 4006.86,3858.37 3992.19,3873.04 ; J28.9@4220.33,3972.22 ccw(c4210.31,3962.2) 4210.31,3976.38 ccw(c4210.31,3990.56) J28.9@4220.33,3980.53 ; J28.9@4248.52,3976.38 4189.66,3976.38 4185,3981.04 4092.52,3981.04 4090.19,3983.37 4065.19,3983.37 4006.86,3925.04 4006.86,3887.71 3992.19,3873.04 ; R171.2@4428.19,3257.08 cw(c4419.59,3245.75) 4433.82,3245.75 ; R171.2@4433.82,3265 4433.82,3245.75 ; R171.2@4439.45,3257.08 ccw(c4448.04,3245.75) 4433.82,3245.75 ; v1(4448.52,3231.04) 4433.82,3245.75 ; 3985.86,3879.37 3992.19,3873.04 ; 3985.86,3879.37 3992.19,3873.04
  MidLayer2 w4: v4(3995,3220) 4017.37,3242.37 4217.5,3242.37 4253.84,3278.71 v1(4353.52,3278.71) ; v4@3995,3225.81 ccw(c3995,3239.84) 4004.92,3229.92 ccw(c4014.84,3220) v4@4000.81,3220 ; v4@3995,3229.81 ccw(c3995,3253.5) 4011.75,3236.75 ccw(c4028.5,3220) v4@4004.81,3220 ; v1@4346.81,3271.99 ccw(c4330.59,3255.77) 4330.59,3278.71 ccw(c4330.59,3301.64) v1@4346.81,3285.43 ; v1@4349.64,3274.82 ccw(c4340.25,3265.43) 4340.25,3278.71 ccw(c4340.25,3291.99) v1@4349.64,3282.6
  Bottom Layer w4: v4@3988.06,3226.94 ccw(c3971.31,3243.69) 3995,3243.69 ccw(c4018.69,3243.69) v4@4001.94,3226.94 ; v4@3990.89,3224.11 ccw(c3980.97,3234.03) 3995,3234.03 ccw(c4009.03,3234.03) v4@3999.11,3224.11 ; v4(3995,3220) 3995,3278.14 4006.86,3290 4006.86,3317.98 4029.52,3340.65 4029.52,3427.37 4017.7,3439.2 4017.7,3460 v4(4017.35,3460.35) ; v4@4011.22,3452.69 cw(c4000.42,3439.2) 4017.7,3439.2 cw(c4036.25,3439.2) v4@4023.89,3453.03 ; v4@4013.72,3455.81 cw(c4007.08,3447.53) 4017.7,3447.53 ; 4017.7,3448.14 cw(c4028.26,3448.14) v4@4021.22,3456.01 ; v1(4353.52,3278.71) 4436.52,3278.71 4448.52,3266.71 v1(4448.52,3231.04) ; v1@4357.41,3274.82 cw(c4366.8,3265.43) 4366.8,3278.71 cw(c4366.8,3291.99) v1@4357.41,3282.6 ; v1@4360.24,3271.99 cw(c4376.46,3255.77) 4376.46,3278.71 cw(c4376.46,3301.64) v1@4360.24,3285.43 ; v1@4441.81,3237.76 ccw(c4425.59,3253.98) 4448.52,3253.98 ccw(c4471.46,3253.98) v1@4455.24,3237.76 ; v1@4444.64,3234.93 ccw(c4435.25,3244.32) 4448.52,3244.32 ccw(c4461.8,3244.32) v1@4452.41,3234.93
LEDS#.LED0.GREEN: J28.11 R172.2 U32.6 | length 1888.6
  Top Layer w4: U32.6@3920,3892.05 3962.2,3892.05 3970.52,3900.37 ; U32.6@3949.31,3889.22 cw(c3956.14,3882.39) 3956.14,3892.05 cw(c3956.14,3901.71) U32.6@3949.31,3894.88 ; v1@3979.02,3895.53 ccw(c3970.52,3890.51) 3970.52,3900.37 ; v1@3979.02,3905.21 cw(c3970.52,3910.24) 3970.52,3900.37 ; v1(3987.19,3900.37) 3970.52,3900.37 ; v1(4173.52,3656.37) 4198.52,3681.37 4274.19,3681.37 4288.86,3666.71 4402.29,3666.71 4403.45,3665.55 4403.45,3623.45 4490.19,3536.71 4519.54,3536.71 4525.19,3531.06 4525.19,3450 4515.19,3440 4515.19,3413.37 4523.52,3405.04 4531.86,3405.04 4540.19,3396.71 4540.19,3370.04 4510.52,3340.37 4439.82,3340.37 4433.82,3334.37 ; v1@4173.52,3661.87 ccw(c4173.52,3675.15) 4182.91,3665.76 ccw(c4192.3,3656.37) v1@4179.02,3656.37 ; v1@4173.52,3665.87 ccw(c4173.52,3688.81) 4189.74,3672.59 ccw(c4205.96,3656.37) v1@4183.02,3656.37 ; v1(4198.52,3933.37) 4202.16,3937.01 J28.11@4246.61,3937.01 ; v1@4199.58,3932.31 cw(c4210.92,3920.98) 4210.92,3937.01 ; v1@4202.41,3929.49 cw(c4220.57,3911.33) J28.11@4220.57,3937.01 ; v1@4205.24,3926.66 cw(c4230.23,3901.67) J28.11@4230.23,3937.01 ; v1@4205.24,3940.09 ccw(c4212.69,3947.54) 4212.69,3937.01 ; J28.11@4220.33,3932.85 ccw(c4210.31,3922.83) 4210.31,3937.01 ccw(c4210.31,3951.19) J28.11@4220.33,3941.16 ; R172.2@4431.98,3332.13 ccw(c4431.53,3334.37) 4433.82,3334.37 ; R172.2@4433.82,3322.5 4433.82,3334.37 ; R172.2@4435.66,3332.13 cw(c4436.11,3334.37) 4433.82,3334.37
  MidLayer1 w4: v1(3987.19,3900.37) 4059.63,3900.37 4095,3865 4095,3800.9 4149.02,3746.88 4173.52,3722.37 v1(4173.52,3656.37) ; v1@3991.08,3896.49 cw(c4000.47,3887.1) 4000.47,3900.37 cw(c4000.47,3913.65) v1@3991.08,3904.26 ; v1@3993.91,3893.66 cw(c4010.13,3877.44) 4010.13,3900.37 cw(c4010.13,3923.31) v1@3993.91,3907.09 ; v1@4166.81,3663.09 ccw(c4150.59,3679.31) 4173.52,3679.31 ccw(c4196.46,3679.31) v1@4180.24,3663.09 ; v1@4169.64,3660.26 ccw(c4160.25,3669.65) 4173.52,3669.65 ccw(c4186.8,3669.65) v1@4177.41,3660.26
  Bottom Layer w4: v1(3987.19,3900.37) 4020.19,3933.37 v1(4198.52,3933.37) ; v1@3987.19,3905.87 ccw(c3987.19,3919.15) 3996.58,3909.76 ccw(c4005.97,3900.37) v1@3992.69,3900.37 ; v1@3987.19,3909.87 ccw(c3987.19,3932.81) 4003.41,3916.59 ccw(c4019.63,3900.37) v1@3996.69,3900.37 ; v1@4191.81,3926.66 ccw(c4175.59,3910.44) 4175.59,3933.37 ccw(c4175.59,3956.31) v1@4191.81,3940.09 ; v1@4194.64,3929.49 ccw(c4185.25,3920.1) 4185.25,3933.37 ccw(c4185.25,3946.65) v1@4194.64,3937.26
LEDS#.LED0.RED: J28.6 R170.2 U32.2 | length 1979.1
  Top Layer w4: v1(3871.19,4000.04) 3876.82,3994.41 U32.2@3920,3994.41 ; v1@3872.25,4001.1 ccw(c3888.41,4017.26) U32.2@3888.41,3994.41 ; v1@3875.08,4003.93 ccw(c3898.06,4026.91) U32.2@3898.06,3994.41 ; v1@3877.91,4006.76 ccw(c3907.72,4036.57) U32.2@3907.72,3994.41 ; U32.2@3890.69,3991.58 ccw(c3883.86,3984.75) 3883.86,3994.41 ccw(c3883.86,4004.07) U32.2@3890.69,3997.24 ; J28.6@4323.39,4035.43 4365.8,4035.43 v1@4373.52,4027.71 ; J28.6@4349.12,4035.43 ccw(c4349.12,4060.44) v1@4366.81,4042.76 ; J28.6@4349.67,4031.28 cw(c4359.69,4021.25) 4359.69,4035.43 cw(c4359.69,4049.61) J28.6@4349.67,4039.59 ; J28.6@4352.06,4035.43 cw(c4352.06,4014.57) 4366.81,4029.32 cw(c4350.59,4013.11) 4373.52,4013.11 cw(c4396.46,4013.11) v1@4380.24,4029.32 ; 4358.78,4035.43 ccw(c4358.78,4050.79) v1@4369.64,4039.93 ; 4361.71,4035.43 cw(c4361.71,4024.23) 4369.64,4032.15 cw(c4360.25,4022.76) 4373.52,4022.76 cw(c4386.8,4022.76) v1@4377.41,4032.15 ; v1(4373.52,4036.04) v1@4373.52,4027.71 ; v1@4401.52,3445.87 cw(c4401.52,3422.94) 4417.74,3439.16 cw(c4433.96,3455.37) v1@4411.02,3455.37 ; v1@4401.52,3449.87 cw(c4401.52,3436.6) 4410.91,3445.99 cw(c4420.3,3455.37) v1@4407.02,3455.37 ; v1(4401.52,3455.37) 4433.82,3423.08 R170.2@4433.82,3380 ; v1@4415.02,3916.71 ccw(c4392.09,3916.71) 4408.31,3932.93 ccw(c4424.52,3949.14) v1@4424.52,3926.21 ; v1@4419.02,3916.71 ccw(c4405.75,3916.71) 4415.14,3926.1 ccw(c4424.52,3935.49) v1@4424.52,3922.21 ; v1(4424.52,3916.71) 4381.86,3959.37 4381.86,3990 4373.52,3998.33 v1@4373.52,4027.71 ; R170.2@4427.23,3387.08 ccw(c4411.32,3402.99) 4433.82,3402.99 ccw(c4456.32,3402.99) R170.2@4440.41,3387.08 ; R170.2@4430.06,3384.25 ccw(c4420.98,3393.33) 4433.82,3393.33 ccw(c4446.66,3393.33) R170.2@4437.58,3384.25
  MidLayer1 w4: v1@4394.81,3462.09 ccw(c4385.83,3471.07) 4398.52,3471.07 ; 4398.52,3475.9 ccw(c4422.04,3475.9) v1@4405.41,3459.26 ; 4398.52,3485.55 ccw(c4431.7,3485.55) v1@4408.24,3462.09 ; v1(4401.52,3455.37) 4398.52,3458.37 4398.52,3531.71 4443.86,3577.04 4443.86,3897.37 v1(4424.52,3916.71) ; v1@4424.52,3907.21 cw(c4424.52,3884.27) 4440.74,3900.49 cw(c4456.96,3916.71) v1@4434.02,3916.71 ; v1@4424.52,3911.21 cw(c4424.52,3897.93) 4433.91,3907.32 cw(c4443.3,3916.71) v1@4430.02,3916.71
  Bottom Layer w4: v1@3871.19,3990.54 cw(c3871.19,3967.61) 3887.41,3983.82 cw(c3903.63,4000.04) v1@3880.69,4000.04 ; v1@3871.19,3994.54 cw(c3871.19,3981.26) 3880.58,3990.65 cw(c3889.97,4000.04) v1@3876.69,4000.04 ; v1(3871.19,4000.04) 3891.19,3980.04 4317.52,3980.04 v1(4373.52,4036.04) ; v1@4364.02,4036.04 cw(c4341.09,4036.04) 4357.31,4019.82 cw(c4373.52,4003.61) v1@4373.52,4026.54 ; v1@4368.02,4036.04 cw(c4354.75,4036.04) 4364.14,4026.65 cw(c4373.52,4017.26) v1@4373.52,4030.54
LEDS#.LED1.BLUE: J28.12 R174.2 U32.10 | length 4019.8
  Top Layer w4: v1@4033.47,3880.09 ccw(c4017.26,3896.31) 4040.19,3896.31 ccw(c4063.13,3896.31) v1@4046.91,3880.09 ; v1@4036.3,3877.26 ccw(c4026.91,3886.65) 4040.19,3886.65 ccw(c4053.47,3886.65) v1@4044.08,3877.26 ; v1(4040.19,3873.37) 4040.19,3915.19 4050.47,3925.46 4092.36,3925.46 4100.19,3917.64 U32.10@4138.5,3917.64 ; U32.10@4109.2,3914.81 ccw(c4102.37,3907.98) 4102.37,3917.64 ccw(c4102.37,3927.3) U32.10@4109.2,3920.47 ; J28.12@4323.39,3917.32 4364.14,3917.32 v1@4366.47,3914.99 ; J28.12@4337.25,3917.32 cw(c4337.25,3879.77) v1@4363.81,3906.32 ; J28.12@4346.91,3917.32 cw(c4346.91,3889.42) v1@4366.64,3909.15 ; J28.12@4349.67,3913.17 cw(c4359.69,3903.14) 4359.69,3917.32 cw(c4359.69,3931.5) J28.12@4349.67,3921.48 ; 4356.57,3917.32 cw(c4356.57,3899.08) v1@4369.46,3911.98 ; 4357.93,3917.32 ccw(c4357.93,3925.64) v1@4363.81,3919.76 ; v1@4366.47,3914.76 v1@4368.19,3913.04 ; R174.2@5137.71,2687.47 cw(c5126.09,2674.08) 5143.82,2674.08 ; R174.2@5140.33,2690.49 cw(c5133.7,2682.85) 5143.82,2682.85 cw(c5153.94,2682.85) R174.2@5147.31,2690.49 ; R174.2@5143.82,2695 5143.82,2674.08 ; R174.2@5149.93,2687.47 ccw(c5161.55,2674.08) 5143.82,2674.08 ; v1(5165.19,2641.71) 5165.19,2652.71 5143.82,2674.08
  MidLayer1 w4: v1@4033.47,2615.09 ccw(c4017.26,2631.31) 4040.19,2631.31 ccw(c4063.13,2631.31) v1@4046.91,2615.09 ; v1@4036.3,2612.26 ccw(c4026.91,2621.65) 4040.19,2621.65 ccw(c4053.47,2621.65) v1@4044.08,2612.26 ; v1(4040.19,2608.37) 4040.19,3063.12 4158.1,3181.03 4257.18,3181.03 4273.52,3197.37 4273.52,3250.04 4280.52,3257.04 4280.52,3823.04 4290.19,3832.71 v1(4370.52,3913.04) ; v1@4361.02,3913.04 cw(c4338.09,3913.04) 4354.31,3896.82 cw(c4370.52,3880.61) v1@4370.52,3903.54 ; v1@4365.02,3913.04 cw(c4351.75,3913.04) 4361.14,3903.65 cw(c4370.52,3894.26) v1@4370.52,3907.54
  MidLayer2 w4: v1@4033.47,2601.66 cw(c4017.26,2585.44) 4040.19,2585.44 cw(c4063.13,2585.44) v1@4046.91,2601.66 ; v1@4035.35,3881.55 ccw(c4030.32,3890.04) 4040.19,3890.04 ; v1@4036.3,2604.49 cw(c4026.91,2595.1) 4040.19,2595.1 cw(c4053.47,2595.1) v1@4044.08,2604.49 ; v1(4040.19,2608.37) 4040.19,2494.81 4060.29,2474.71 4428.54,2474.71 4529.4,2575.56 4612.52,2575.56 4687,2650.04 4899.51,2650.04 4933.17,2616.37 5061.37,2616.37 5095,2650 5113.37,2650 5121.67,2641.71 v1(5165.19,2641.71) ; v1(4040.19,3873.37) 4040.19,3890.04 ; v1@4045.03,3881.55 cw(c4050.06,3890.04) 4040.19,3890.04 ; v1@4361.02,3913.04 ccw(c4338.09,3913.04) 4354.31,3929.26 ccw(c4370.52,3945.48) v1@4370.52,3922.54 ; v1@4365.02,3913.04 ccw(c4351.75,3913.04) 4361.14,3922.43 ccw(c4370.52,3931.82) v1@4370.52,3918.54 ; v1(4370.52,3913.04) 4325.19,3958.37 4108.52,3958.37 4040.19,3890.04 ; v1@5158.47,2634.99 ccw(c5142.26,2618.77) 5142.26,2641.71 ccw(c5142.26,2664.64) v1@5158.47,2648.43 ; v1@5161.3,2637.82 ccw(c5151.91,2628.43) 5151.91,2641.71 ccw(c5151.91,2654.99) v1@5161.3,2645.6
LEDS#.LED1.GREEN: J28.8 R175.2 U32.12 | length 3239
  Top Layer w4: U32.12@4109.2,3965.99 ccw(c4102.37,3959.16) 4102.37,3968.82 ccw(c4102.37,3978.48) U32.12@4109.2,3971.65 ; U32.12@4138.5,3968.82 4088.08,3968.82 4081.86,3975.04 4068.17,3975.04 4015.19,3922.06 4015.19,3858.37 4056.86,3816.71 4148.52,3816.71 4190.19,3858.37 4190.19,3891.71 4215.19,3916.71 4273.19,3916.71 4289.86,3933.37 4350.86,3933.37 4365.19,3947.71 ; J28.8@4323.39,3996.06 4355.39,3996.06 ; J28.8@4350.67,3993.26 cw(c4355.39,3990.7) 4355.39,3996.06 ; J28.8@4350.67,3998.87 ccw(c4355.39,4001.42) 4355.39,3996.06 ; v1(4681.86,2600.04) 4698.86,2617.04 4698.86,2746.73 4581.86,2863.73 4581.86,3000.04 4615.19,3033.37 4615.19,3475.04 4606.86,3483.37 4606.86,3550 4588.15,3568.71 4503.45,3568.71 4465.19,3606.96 4465.19,3772.67 4443.86,3794 4443.86,3869.04 4365.19,3947.71 ; v1@4681.86,2605.54 ccw(c4681.86,2618.82) 4691.25,2609.43 ccw(c4700.64,2600.04) v1@4687.36,2600.04 ; v1@4681.86,2609.54 ccw(c4681.86,2632.48) 4698.07,2616.26 ccw(c4714.29,2600.04) v1@4691.36,2600.04 ; R175.2@5138.56,2749.31 cw(c5131.76,2739.36) 5143.82,2739.36 ; R175.2@5143.82,2757.5 5143.82,2739.35 ; R175.2@5149.08,2749.31 ccw(c5155.88,2739.36) 5143.82,2739.36 ; v1(5190.19,2591.71) 5190.19,2591.96 5147.69,2634.46 5147.69,2658.89 5126.5,2680.08 5126.5,2722.04 5142.15,2737.69 5143.82,2739.35 ; 4355.39,3996.06 4365.19,3986.26 4365.19,3947.71
  MidLayer2 w4: v1(4681.86,2600.04) 5141.87,2600.04 5150.21,2591.71 v1(5190.19,2591.71) ; v1@4685.75,2596.15 cw(c4695.14,2586.76) 4695.14,2600.04 cw(c4695.14,2613.32) v1@4685.75,2603.93 ; v1@4688.57,2593.32 cw(c4704.79,2577.11) 4704.79,2600.04 cw(c4704.79,2622.98) v1@4688.57,2606.76 ; v1@5183.47,2584.99 ccw(c5167.26,2568.77) 5167.26,2591.71 ccw(c5167.26,2614.64) v1@5183.47,2598.43 ; v1@5186.3,2587.82 ccw(c5176.91,2578.43) 5176.91,2591.71 ccw(c5176.91,2604.99) v1@5186.3,2595.6
LEDS#.LED1.RED: J28.10 R173.2 U32.8 | length 2967
  Top Layer w4: U32.8@4112.02,3866.46 cw(c4097.91,3845.08) v1@4123.52,3845.08 ; U32.8@4114.23,3869.8 cw(c4102.82,3852.52) 4123.52,3852.52 ; v1@4117.43,3847.33 ccw(c4106.51,3860.37) 4123.52,3860.37 ; v1@4120,3844.26 ccw(c4113.68,3851.81) 4123.52,3851.81 ccw(c4133.37,3851.81) v1@4127.05,3844.26 ; 4123.33,3860.37 ccw(c4123.33,3864.97) U32.8@4127.89,3864.37 ; v1(4123.52,3840.04) 4123.52,3860.37 ; 4127.9,3860.37 ccw(c4127.9,3864.36) U32.8@4131.85,3863.84 ; v1@4129.62,3847.33 cw(c4140.53,3860.37) 4123.52,3860.37 ; 4132.46,3860.37 ccw(c4132.46,3863.76) U32.8@4135.82,3863.32 ; U32.8@4136.92,3862.79 cw(c4135.88,3860.38) 4138.5,3860.38 cw(c4141.13,3860.38) U32.8@4140.09,3862.79 ; 4137.02,3860.37 ccw(c4137.02,3863.16) U32.8@4139.78,3862.8 ; U32.8@4138.5,3866.46 4123.52,3866.46 4123.52,3860.37 ; U32.8@4164.01,3862.58 ccw(c4165.77,3869.58) U32.8@4170.88,3864.48 ; U32.8@4164.98,3866.46 ccw(c4167.77,3877.56) 4175.87,3869.47 ; U32.8@4165.96,3870.34 ccw(c4169.77,3885.54) 4180.86,3874.46 ; J28.10@4297.11,3952.54 ccw(c4287.08,3942.51) 4287.08,3956.69 ccw(c4287.08,3970.87) J28.10@4297.11,3960.85 ; J28.10@4323.39,3956.69 4190.19,3956.69 4180.86,3947.36 4180.86,3874.46 ; v1(5098.19,2816.37) 5103.9,2816.37 5107.52,2820 R173.2@5143.82,2820 ; v1@5099.25,2815.31 cw(c5110.56,2804) 5110.56,2820 ; v1@5102.08,2812.49 cw(c5120.22,2794.35) 5120.22,2820 ; v1@5104.91,2809.66 cw(c5129.88,2784.69) 5129.88,2820 ; v1@5104.91,2823.09 ccw(c5112.37,2830.56) 5112.37,2820 ; R173.2@5137.23,2813.41 ccw(c5121.32,2797.5) 5121.32,2820 ccw(c5121.32,2842.5) R173.2@5137.23,2826.59 ; R173.2@5140.06,2816.24 ccw(c5130.98,2807.16) 5130.98,2820 ccw(c5130.98,2832.84) R173.2@5140.06,2823.76 ; 4123.52,3860.37 4166.77,3860.37 4180.86,3874.46
  MidLayer2 w4: v1@4051.81,3515.09 ccw(c4035.59,3531.31) 4058.52,3531.31 ccw(c4081.46,3531.31) v1@4065.24,3515.09 ; v1@4054.64,3512.26 ccw(c4045.25,3521.65) 4058.52,3521.65 ccw(c4071.8,3521.65) v1@4062.41,3512.26 ; v1(4058.52,3508.37) 4058.52,3560 4089.69,3591.17 4089.69,3652.27 4123.52,3686.1 v1(4123.52,3840.04) ; v1@4116.81,3833.32 cw(c4100.59,3817.11) 4123.52,3817.11 cw(c4146.46,3817.11) v1@4130.24,3833.32 ; v1@4119.64,3836.15 cw(c4110.25,3826.76) 4123.52,3826.76 cw(c4136.8,3826.76) v1@4127.41,3836.15
  Bottom Layer w4: v1@4051.81,3501.66 cw(c4044.1,3493.95) 4055,3493.95 ; 4055,3476.93 cw(c4089.97,3476.93) v1@4065.24,3501.66 ; 4055,3486.59 cw(c4080.31,3486.59) v1@4062.41,3504.49 ; 4055,3496.25 cw(c4070.65,3496.25) v1@4059.58,3507.31 ; v1(4058.52,3508.37) 4055,3504.85 4055,3470 4085,3440 4085,3420 ; 4085.07,3419.93 4053.52,3388.37 4053.52,3324.98 4060.19,3318.31 4060.19,3030.04 4115.19,2975.04 4411.86,2975.04 4477.86,2909.04 4650.96,2909.04 4751.63,2808.37 5090.19,2808.37 v1(5098.19,2816.37) ; 5055.94,2808.37 ccw(c5055.94,2858.62) v1@5091.47,2823.09 ; 5065.6,2808.37 ccw(c5065.6,2848.97) v1@5094.3,2820.26 ; 5075.26,2808.37 ccw(c5075.26,2839.31) v1@5097.13,2817.44 ; 5084.91,2808.37 ccw(c5084.91,2829.65) v1@5099.96,2814.61
LEDS#.LED2.BLUE: J28.16 R177.2 U33.4 | length 2334.2
  Top Layer w4: J28.16@4323.39,3838.58 4418.32,3838.58 4431.86,3825.04 4431.86,3794.69 4456.86,3769.69 4456.86,3603.98 4500.13,3560.71 4533.48,3560.71 4559.19,3535 4559.19,3347.71 4573.52,3333.37 4590.19,3333.37 4598.52,3325.04 4598.52,3244.71 v1(4565.19,3211.37) ; J28.16@4349.67,3834.43 cw(c4359.69,3824.4) 4359.69,3838.58 cw(c4359.69,3852.76) J28.16@4349.67,3842.74 ; v1@4565.19,3216.87 ccw(c4565.19,3230.15) 4574.58,3220.76 ccw(c4583.97,3211.37) v1@4570.69,3211.37 ; v1@4565.19,3220.87 ccw(c4565.19,3243.81) 4581.41,3227.59 ccw(c4597.63,3211.37) v1@4574.69,3211.37 ; v1@5007.47,3015.09 ccw(c4991.26,3031.31) 5014.19,3031.31 ccw(c5037.13,3031.31) v1@5020.91,3015.09 ; v1@5010.3,3012.26 ccw(c5000.91,3021.65) 5014.19,3021.65 ccw(c5027.47,3021.65) v1@5018.08,3012.26 ; v1(5014.19,3008.37) 5014.19,3054.19 5048.23,3088.23 U33.4@5125,3088.23 ; U33.4@5095.69,3085.4 ccw(c5088.86,3078.57) 5088.86,3088.23 ccw(c5088.86,3097.88) U33.4@5095.69,3091.06
  Bottom Layer w4: R177.2@4414.59,3077.92 cw(c4398.68,3062.01) 4421.18,3062.01 cw(c4443.68,3062.01) R177.2@4427.77,3077.92 ; R177.2@4416.81,3093.72 ccw(c4412.95,3100.99) 4421.18,3100.99 ; R177.2@4417.42,3080.75 cw(c4408.34,3071.67) 4421.18,3071.67 cw(c4434.02,3071.67) R177.2@4424.94,3080.75 ; R177.2@4425.55,3093.72 cw(c4429.41,3100.99) 4421.18,3100.99 ; 4556.86,3168.32 cw(c4608.24,3168.32) v1@4571.91,3204.66 ; 4556.86,3177.98 cw(c4598.59,3177.98) v1@4569.08,3207.49 ; 4556.86,3187.64 cw(c4588.93,3187.64) v1@4566.25,3210.31 ; 4556.86,3197.29 cw(c4579.27,3197.29) v1@4563.42,3213.14 ; v1(4565.19,3211.37) 4556.86,3203.04 4556.86,3166.71 4548.52,3158.37 4520.54,3158.37 4507.88,3171.04 4485,3171.04 4472.5,3171.04 4443.5,3142.03 4443.5,3123.31 4421.18,3100.99 ; v1@5007.47,3001.66 ccw(c4991.26,2985.44) 4991.26,3008.37 ccw(c4991.26,3031.31) v1@5007.47,3015.09 ; v1@5010.3,3004.49 ccw(c5000.91,2995.1) 5000.91,3008.37 ccw(c5000.91,3021.65) v1@5010.3,3012.26 ; v1(5014.19,3008.37) 4965.13,3008.37 4921.8,2965.04 4606.86,2965.04 4538.52,3033.37 4443.52,3033.37 4421.18,3055.72 R177.2@4421.18,3085 4421.18,3100.99
LEDS#.LED2.GREEN: J28.18 R178.2 U33.6 | length 2771.4
  Top Layer w4: J28.18@4323.39,3799.21 4361.39,3799.21 4413.18,3747.42 4422.52,3738.07 v1(4422.52,3691.71) ; J28.18@4349.67,3795.06 cw(c4359.69,3785.03) 4359.69,3799.21 cw(c4359.69,3813.39) J28.18@4349.67,3803.37 ; v1@4415.81,3698.43 ccw(c4399.59,3714.64) 4422.52,3714.64 ccw(c4445.46,3714.64) v1@4429.24,3698.43 ; v1@4418.64,3695.6 ccw(c4409.25,3704.99) 4422.52,3704.99 ccw(c4435.8,3704.99) v1@4426.41,3695.6 ; U33.6@5125,3037.05 5162.85,3037.05 5173.52,3026.37 ; U33.6@5154.31,3034.22 cw(c5161.14,3027.39) 5161.14,3037.05 cw(c5161.14,3046.7) U33.6@5154.31,3039.88 ; v1@5168.17,3016.22 ccw(c5161.23,3026.37) 5173.52,3026.37 ; v1(5173.52,3008.37) 5173.52,3026.37 ; v1@5178.88,3016.22 cw(c5185.82,3026.37) 5173.52,3026.37
  Bottom Layer w4: 4404.43,3125.13 cw(c4421.18,3108.38) R178.2@4421.18,3132.06 ; 4405.62,3126.31 ccw(c4390.55,3141.38) R178.2@4411.86,3141.38 ; R178.2@4411.26,3131.96 cw(c4421.18,3122.04) R178.2@4421.18,3136.06 ; R178.2@4412.45,3133.14 ccw(c4404.21,3141.38) R178.2@4415.86,3141.38 ; v1@4413.02,3691.71 cw(c4390.09,3691.71) 4406.31,3675.49 cw(c4422.52,3659.27) v1@4422.52,3682.21 ; v1@4417.02,3691.71 cw(c4403.75,3691.71) 4413.14,3682.32 cw(c4422.52,3672.93) v1@4422.52,3686.21 ; v1(4422.52,3691.71) 4405.86,3675.04 4123.52,3675.04 4090.19,3641.71 4090.19,3600.04 4131.19,3559.04 4131.19,3489.39 4140.52,3480.06 4140.52,3199.71 4231.86,3108.37 4387.68,3108.37 R178.2@4421.18,3141.88 4432.02,3141.88 4469.52,3179.37 4510.86,3179.37 4521.02,3169.21 4539.21,3169.21 4547.19,3177.19 4547.19,3242.27 4579.96,3275.04 4627.86,3275.04 4631.86,3271.04 4631.86,3133.37 4648.52,3116.71 4698.52,3116.71 4740.19,3075.04 4740.19,3050.37 4756.86,3033.71 4945.21,3033.71 4986.54,3075.04 5074.13,3075.04 5140.8,3008.37 v1(5173.52,3008.37) ; v1@5166.81,3001.66 ccw(c5150.59,2985.44) 5150.59,3008.37 ccw(c5150.59,3031.31) v1@5166.81,3015.09 ; v1@5169.64,3004.49 ccw(c5160.25,2995.1) 5160.25,3008.37 ccw(c5160.25,3021.65) v1@5169.64,3012.26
